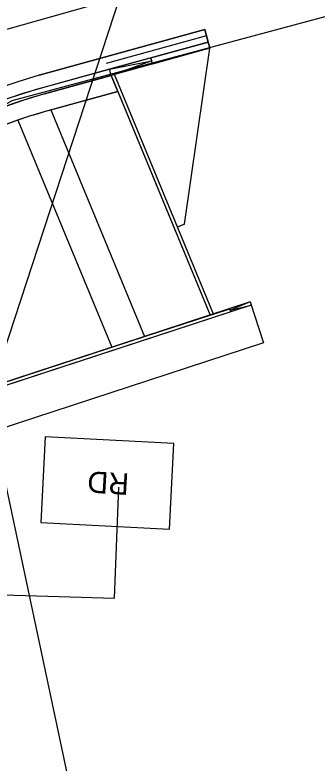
# Model space of a CAD drawing. Extents: x -728802 to -728097, y -1073200 to -1072700.
# Drawn here: x -728493.61 to -728486.57, y -1073043.37 to -1073025.94 of the extents above; entities that cross this region are included whole.
import ezdxf

# ---------------------------------------------------------------- set-up
doc = ezdxf.new("R2010")
doc.units = 0
for name, color, linetype in [('3_třída_přesnosti', 7, 'Continuous'), ('_popis', 7, 'Continuous'), ('Hranice parcel', 7, 'Continuous'), ('Projekt', 7, 'Continuous'), ('ZZZ_popisky', 7, 'Continuous')]:
    doc.layers.add(name, color=color, linetype=linetype)

msp = doc.modelspace()

# ---------------------------------------------------------------- linework, layer by layer
at = {"layer": '3_třída_přesnosti'}
msp.add_lwpolyline([(-728443.68, -1073014.51), (-728468.68, -1073021.225), (-728493.68, -1073027.94), (-728497.54, -1073030.15), (-728499.78, -1073032.61), (-728501.19, -1073037.94)], dxfattribs=at)
at = {"layer": '_popis'}
for points in [[(-728495.968, -1073026.894), (-728333.51, -1072980.651), (-728306.876, -1073003.138), (-728232.142, -1073001.126), (-728100, -1072919.194)], [(-728100, -1073009.894), (-728187.96, -1073038.534), (-728349.393, -1073048.737), (-728486.186, -1073072.542), (-728495.968, -1073026.894)]]:
    msp.add_lwpolyline(points, dxfattribs=at)
at = {"layer": 'Hranice parcel'}
msp.add_circle((-728505.883, -1073042.015), 62.481, dxfattribs=at)
at = {"layer": 'Projekt'}
for p, q in [((-728489.068, -1073026.719), (-728489.108, -1073026.574)), ((-728489.66, -1073030.819), (-728489.068, -1073026.719)), ((-728491.408, -1073027.208), (-728490.424, -1073027.015)), ((-728490.424, -1073027.015), (-728491.368, -1073027.353)), ((-728490.404, -1073027.087), (-728490.444, -1073026.942)), ((-728491.368, -1073027.353), (-728491.408, -1073027.208)), ((-728491.368, -1073027.353), (-728489.062, -1073032.933)), ((-728492.771, -1073028.155), (-728490.59, -1073033.433)), ((-728493.539, -1073028.392), (-728491.352, -1073033.682)), ((-728489.66, -1073030.819), (-728489.821, -1073030.886)), ((-728488.131, -1073032.628), (-728488.594, -1073032.822)), ((-728488.594, -1073032.822), (-728488.106, -1073032.704)), ((-728488.131, -1073032.628), (-728487.82, -1073033.579))]:
    msp.add_line(p, q, dxfattribs=at)
for points in [[(-728493.044, -1073027.348), (-728489.188, -1073026.285), (-728489.108, -1073026.574), (-728491.408, -1073027.208), (-728492.964, -1073027.637)], [(-728489.108, -1073026.574), (-728489.188, -1073026.285), (-728493.044, -1073027.348)], [(-728489.148, -1073026.429), (-728491.483, -1073027.074)], [(-728489.108, -1073026.574), (-728492.964, -1073027.637)], [(-728490.444, -1073026.942), (-728489.108, -1073026.574), (-728489.068, -1073026.719), (-728490.404, -1073027.087), (-728490.424, -1073027.015), (-728490.444, -1073026.942)], [(-728489.068, -1073026.719), (-728492.924, -1073027.782)], [(-728492.924, -1073027.782), (-728491.368, -1073027.353), (-728491.408, -1073027.208), (-728492.964, -1073027.637)], [(-728492.818, -1073028.168), (-728492.771, -1073028.155), (-728491.214, -1073027.725), (-728491.368, -1073027.353), (-728492.924, -1073027.782)], [(-728488.985, -1073032.908), (-728491.29, -1073027.331), (-728491.368, -1073027.353), (-728491.214, -1073027.725), (-728489.062, -1073032.933), (-728488.985, -1073032.908)], [(-728488.985, -1073032.908), (-728491.29, -1073027.331)], [(-728491.214, -1073027.725), (-728492.818, -1073028.168)], [(-728488.131, -1073032.628), (-728496.655, -1073035.417)], [(-728488.106, -1073032.704), (-728496.63, -1073035.493)], [(-728496.655, -1073035.417), (-728491.352, -1073033.682), (-728490.59, -1073033.433), (-728489.062, -1073032.933), (-728488.985, -1073032.908), (-728488.606, -1073032.784), (-728488.594, -1073032.822), (-728488.581, -1073032.86), (-728496.554, -1073035.468), (-728496.63, -1073035.493), (-728496.655, -1073035.417), (-728496.655, -1073035.417)], [(-728488.581, -1073032.86), (-728488.606, -1073032.784)], [(-728487.82, -1073033.579), (-728495.393, -1073036.056)], [(-728494.829, -1073039.422), (-728493.88, -1073039.45), (-728491.292, -1073039.525), (-728491.192, -1073036.939)]]:
    msp.add_lwpolyline(points, dxfattribs=at)
msp.add_lwpolyline([(-728489.907, -1073035.925), (-728492.903, -1073035.767), (-728493.008, -1073037.764), (-728490.012, -1073037.922)], close=True, dxfattribs=at)
for radius, start, end in [(12.3, 105.42, 180.2086), (12.3, 105.42, 180.2086), (12, 105.42, 180.2086), (12, 105.42, 117.0974), (12, 105.42, 117.0974), (11.85, 105.42, 180.2086), (11.85, 105.42, 117.0974), (11.85, 105.42, 117.0974), (11.45, 105.42, 117.2893), (11.45, 105.42, 109.1994), (11.45, 109.1994, 117.2893)]:
    msp.add_arc((-728489.773, -1073039.206), radius, start, end, dxfattribs=at)
at = {"layer": 'ZZZ_popisky'}
msp.add_lwpolyline([(-728496.069, -1073040.506), (-728413.218, -1072787.634), (-728463.108, -1072771.288)], dxfattribs=at)

# ---------------------------------------------------------------- texts
at = {"layer": 'Projekt'}
msp.add_text('RD', height=0.5, rotation=176.5903, dxfattribs=at).set_placement((-728490.939, -1073036.625))

doc.saveas('drawing.dxf')
